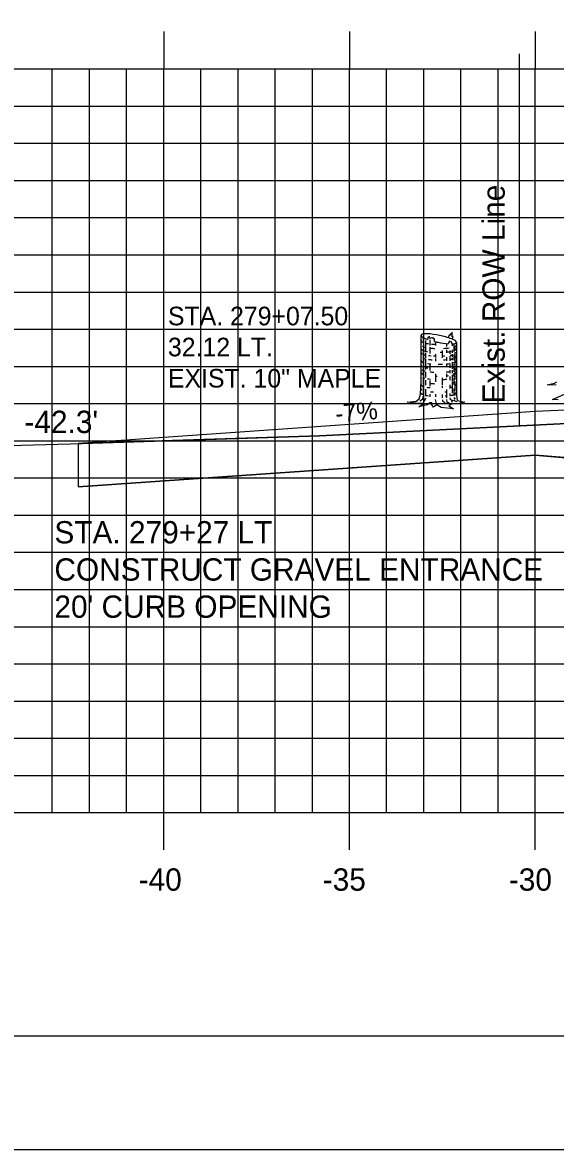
# Model space of a CAD drawing. Extents: x 854899 to 855069, y 366268 to 366378.
# Drawn here: x 854937.97 to 854952.32, y 366268.18 to 366298.48 of the extents above; entities that cross this region are included whole.
import ezdxf

# ---------------------------------------------------------------- set-up
doc = ezdxf.new("R2010")
doc.units = 0
for name, color, linetype in [('ANNOTATION', 7, 'Continuous'), ('BORDER', 7, 'Continuous'), ('D_Roadway_Drive_Gravel_LT', 7, 'Continuous'), ('D_Roadway_Drive_Gravel_RT', 7, 'Continuous'), ('D_Roadway_Drive_SubGrade', 7, 'Continuous'), ('D_Text_Monospaced', 7, 'Continuous'), ('D_Text_Standard', 7, 'Continuous'), ('E_ROW_Line', 7, 'Continuous'), ('H_V ANNOTATION', 7, 'Continuous'), ('JUNK COM EXC', 7, 'Continuous'), ('MAJOR', 7, 'Continuous'), ('MINOR', 7, 'Continuous'), ('PLOT BOUNDARY', 7, 'Continuous'), ('S_Roadway_Centerline', 7, 'Continuous'), ('S_Trees_Decid_NonPay', 7, 'Continuous'), ('S_Trees_Decid_Pay', 7, 'Continuous')]:
    doc.layers.add(name, color=color, linetype=linetype)

msp = doc.modelspace()

# ---------------------------------------------------------------- linework, layer by layer
at = {"layer": 'BORDER'}
msp.add_line((854906.774, 366271.236), (855066.774, 366271.236), dxfattribs=at)
at = {"layer": 'D_Roadway_Drive_Gravel_RT'}
for p, q in [((854957.774, 366288.264), (854951.774, 366288.024)), ((854951.774, 366288.024), (854939.471, 366287.163)), ((854951.774, 366286.853), (854939.471, 366285.996))]:
    msp.add_line(p, q, dxfattribs=at)
at = {"layer": 'D_Roadway_Drive_SubGrade'}
for p, q in [((854939.471, 366287.163), (854939.471, 366285.996)), ((854961.774, 366285.991), (854951.774, 366286.853))]:
    msp.add_line(p, q, dxfattribs=at)
at = {"layer": 'E_ROW_Line'}
msp.add_line((854951.351, 366287.638), (854951.351, 366297.638), dxfattribs=at)
at = {"layer": 'JUNK COM EXC'}
msp.add_lwpolyline([(854961.774, 366285.991), (854961.774, 366288.084), (854961.286, 366288.106), (854961.059, 366288.051), (854957.486, 366287.942), (854945.963, 366287.37), (854939.471, 366287.163), (854939.471, 366285.996), (854951.774, 366286.853)], close=True, dxfattribs=at)
at = {"layer": 'MAJOR'}
for p, q in [((854941.774, 366298.238), (854941.774, 366297.236)), ((854946.774, 366298.238), (854946.774, 366297.236)), ((854951.774, 366298.238), (854951.774, 366297.236)), ((854911.774, 366297.236), (855051.774, 366297.236)), ((854911.774, 366297.236), (855051.774, 366297.236)), ((854941.774, 366277.236), (854941.774, 366297.236)), ((854946.774, 366277.236), (854946.774, 366297.236)), ((854951.774, 366277.236), (854951.774, 366297.236)), ((854911.774, 366292.236), (855051.774, 366292.236)), ((854911.774, 366287.236), (855051.774, 366287.236)), ((854911.774, 366282.236), (855051.774, 366282.236)), ((854911.774, 366277.236), (855051.774, 366277.236)), ((854911.774, 366277.236), (855051.774, 366277.236)), ((854941.774, 366276.234), (854941.774, 366277.236)), ((854946.774, 366276.234), (854946.774, 366277.236)), ((854951.774, 366276.234), (854951.774, 366277.236))]:
    msp.add_line(p, q, dxfattribs=at)
at = {"layer": 'MINOR'}
for p, q in [((854938.774, 366277.236), (854938.774, 366297.236)), ((854939.774, 366277.236), (854939.774, 366297.236)), ((854940.774, 366277.236), (854940.774, 366297.236)), ((854942.774, 366277.236), (854942.774, 366297.236)), ((854943.774, 366277.236), (854943.774, 366297.236)), ((854944.774, 366277.236), (854944.774, 366297.236)), ((854945.774, 366277.236), (854945.774, 366297.236)), ((854947.774, 366277.236), (854947.774, 366297.236)), ((854948.774, 366277.236), (854948.774, 366297.236)), ((854949.774, 366277.236), (854949.774, 366297.236)), ((854950.774, 366277.236), (854950.774, 366297.236)), ((854911.774, 366296.236), (855051.774, 366296.236)), ((854911.774, 366295.236), (855051.774, 366295.236)), ((854911.774, 366294.236), (855051.774, 366294.236)), ((854911.774, 366293.236), (855051.774, 366293.236)), ((854911.774, 366291.236), (855051.774, 366291.236)), ((854911.774, 366290.236), (855051.774, 366290.236)), ((854911.774, 366289.236), (855051.774, 366289.236)), ((854911.774, 366288.236), (855051.774, 366288.236)), ((854911.774, 366286.236), (855051.774, 366286.236)), ((854911.774, 366285.236), (855051.774, 366285.236)), ((854911.774, 366284.236), (855051.774, 366284.236)), ((854911.774, 366283.236), (855051.774, 366283.236)), ((854911.774, 366281.236), (855051.774, 366281.236)), ((854911.774, 366280.236), (855051.774, 366280.236)), ((854911.774, 366279.236), (855051.774, 366279.236)), ((854911.774, 366278.236), (855051.774, 366278.236))]:
    msp.add_line(p, q, dxfattribs=at)
at = {"layer": 'PLOT BOUNDARY'}
msp.add_lwpolyline([(854898.681, 366268.177), (855068.681, 366268.177), (855068.681, 366378.177), (854898.681, 366378.177)], close=True, dxfattribs=at)
at = {"layer": 'S_Roadway_Centerline'}
msp.add_lwpolyline([(854920.631, 366286.642), (854924.888, 366286.755), (854939.58, 366287.166), (854945.963, 366287.37), (854957.486, 366287.942), (854961.059, 366288.051), (854961.286, 366288.106), (854963.414, 366288.013), (854965.316, 366287.948), (854966.506, 366288), (854971.338, 366288.32), (854977.246, 366288.416), (854982.457, 366288.64), (854989.068, 366288.497), (854993.573, 366288.403), (854996.105, 366288.282), (854996.433, 366288.257), (854999.77, 366288.409), (854999.893, 366288.419), (855006.72, 366288.819), (855009.438, 366288.75)], dxfattribs=at)
at = {"layer": 'S_Trees_Decid_NonPay'}
for p, q in [((854948.753, 366290.016), (854948.753, 366289.922)), ((854948.753, 366289.695), (854948.753, 366289.613)), ((854948.821, 366289.929), (854948.821, 366289.629)), ((854948.94, 366289.947), (854948.94, 366289.798)), ((854948.94, 366289.75), (854948.94, 366289.582)), ((854949.087, 366289.901), (854949.087, 366289.794)), ((854949.267, 366289.664), (854949.267, 366289.464)), ((854949.384, 366289.848), (854949.384, 366289.769)), ((854949.384, 366289.683), (854949.384, 366289.598)), ((854949.471, 366289.664), (854949.471, 366289.578)), ((854949.541, 366289.838), (854949.541, 366289.786)), ((854949.541, 366289.683), (854949.541, 366289.6)), ((854949.584, 366289.843), (854949.584, 366289.625)), ((854949.611, 366289.773), (854949.611, 366289.691)), ((854948.753, 366289.543), (854948.753, 366289.292)), ((854948.821, 366289.6), (854948.821, 366289.469)), ((854948.821, 366289.435), (854948.821, 366289.154)), ((854949.087, 366289.565), (854949.087, 366289.479)), ((854949.087, 366289.444), (854949.087, 366289.374)), ((854949.384, 366289.487), (854949.384, 366289.386)), ((854949.471, 366289.508), (854949.471, 366289.386)), ((854949.541, 366289.565), (854949.541, 366289.491)), ((854949.541, 366289.464), (854949.541, 366289.405)), ((854949.541, 366289.351), (854949.541, 366289.17)), ((854949.584, 366289.556), (854949.584, 366289.405)), ((854949.611, 366289.621), (854949.611, 366289.491)), ((854949.611, 366289.469), (854949.611, 366289.287)), ((854948.753, 366289.209), (854948.753, 366288.979)), ((854948.821, 366289.084), (854948.821, 366288.939)), ((854948.94, 366289.275), (854948.94, 366289.127)), ((854949.384, 366289.301), (854949.384, 366289.225)), ((854949.471, 366289.311), (854949.471, 366289.197)), ((854949.471, 366289.135), (854949.471, 366289.053)), ((854949.541, 366289.139), (854949.541, 366289.057)), ((854949.584, 366289.3), (854949.584, 366289.221)), ((854949.584, 366289.195), (854949.584, 366289.088)), ((854949.584, 366289.053), (854949.584, 366288.952)), ((854949.611, 366289.24), (854949.611, 366288.993)), ((854948.753, 366288.908), (854948.753, 366288.748)), ((854948.821, 366288.869), (854948.821, 366288.727)), ((854948.94, 366288.857), (854948.94, 366288.704)), ((854949.087, 366289.04), (854949.087, 366288.818)), ((854949.267, 366288.927), (854949.267, 366288.74)), ((854949.384, 366289.04), (854949.384, 366288.943)), ((854949.471, 366288.966), (854949.471, 366288.869)), ((854949.471, 366288.74), (854949.471, 366288.641)), ((854949.541, 366289.003), (854949.541, 366288.832)), ((854949.541, 366288.799), (854949.541, 366288.519)), ((854949.584, 366288.926), (854949.584, 366288.744)), ((854949.611, 366288.974), (854949.611, 366288.88)), ((854949.613, 366288.826), (854949.612, 366288.567)), ((854948.753, 366288.731), (854948.753, 366288.626)), ((854948.753, 366288.59), (854948.753, 366288.466)), ((854948.821, 366288.626), (854948.821, 366288.445)), ((854948.94, 366288.492), (854948.94, 366288.414)), ((854949.087, 366288.485), (854949.087, 366288.418)), ((854949.267, 366288.709), (854949.267, 366288.656)), ((854949.267, 366288.48), (854949.267, 366288.389)), ((854949.384, 366288.618), (854949.384, 366288.394)), ((854949.471, 366288.511), (854949.471, 366288.453)), ((854949.541, 366288.467), (854949.541, 366288.441)), ((854949.584, 366288.641), (854949.584, 366288.449)), ((854949.611, 366288.528), (854949.611, 366288.454)), ((854948.82, 366288.385), (854948.779, 366288.289)), ((854949.127, 366288.198), (854949.092, 366288.344)), ((854949.582, 366288.402), (854949.617, 366288.351)), ((854949.664, 366288.28), (854949.597, 366288.311))]:
    msp.add_line(p, q, dxfattribs=at)
for points in [[(854949.652, 366289.88), (854949.652, 366288.468), (854949.675, 366288.32), (854949.878, 366288.277), (854949.738, 366288.241), (854949.52, 366288.223), (854949.45, 366288.179), (854949.572, 366288.091), (854949.24, 366288.134), (854949.127, 366288.198), (854949.034, 366288.138), (854948.978, 366288.217), (854948.987, 366288.254), (854948.925, 366288.256), (854948.873, 366288.198), (854948.641, 366288.147), (854948.768, 366288.235), (854948.637, 366288.237), (854948.328, 366288.275), (854948.567, 366288.305), (854948.645, 366288.363), (854948.684, 366288.485), (854948.701, 366288.838), (854948.701, 366290.072)], [(854949.065, 366289.906), (854949.057, 366289.973), (854949.032, 366289.977), (854949.024, 366290.012), (854948.993, 366289.998), (854948.978, 366290.012), (854948.954, 366289.989), (854948.931, 366289.998), (854948.919, 366290.047), (854948.911, 366290.004), (854948.88, 366290.012), (854948.877, 366289.961)], [(854949.557, 366289.961), (854949.553, 366290.055), (854949.539, 366290.029), (854949.539, 366290.15), (854949.518, 366290.086), (854949.503, 366290.119), (854949.487, 366290.063), (854949.471, 366290.08), (854949.452, 366290.072), (854949.433, 366290.005)], [(854949.535, 366289.837), (854949.518, 366289.899), (854949.496, 366289.887), (854949.465, 366289.922), (854949.431, 366289.843)], [(854948.75, 366288.423), (854948.742, 366288.346), (854948.663, 366288.297)], [(854949.275, 366288.34), (854949.275, 366288.303), (854949.326, 366288.273), (854949.343, 366288.223)], [(854949.387, 366288.346), (854949.392, 366288.277), (854949.456, 366288.264)], [(854949.534, 366288.311), (854949.491, 366288.346), (854949.483, 366288.394)], [(854949.613, 366288.328), (854949.534, 366288.311), (854949.518, 366288.268)]]:
    msp.add_lwpolyline(points, dxfattribs=at)
for centre, radius, start, end in [((854948.719, 366290.072), 0.0179, 168.1723, 184.2278), ((854948.725, 366290.072), 0.0237, 184.2278, 198.1723), ((854948.719, 366290.072), 0.0179, 152.1168, 168.1723), ((854948.734, 366290.075), 0.0336, 198.1723, 216.9486), ((854948.724, 366290.069), 0.0237, 138.1723, 152.1168), ((854948.732, 366290.063), 0.0336, 119.396, 138.1723), ((854948.782, 366290.111), 0.0935, 216.9486, 228.1723), ((854948.761, 366290.01), 0.0935, 108.1723, 119.396), ((854948.934, 366290.282), 0.322, 228.1723, 250.2902), ((854948.832, 366289.793), 0.322, 86.0543, 108.1723), ((854949.671, 366292.339), 2.507, 250.2902, 251.5281), ((854948.682, 366287.614), 2.507, 78.1723, 86.0543), ((854948.682, 366287.614), 2.507, 70.2902, 78.1723), ((854949.419, 366289.671), 0.322, 48.1723, 70.2902), ((854948.719, 366289.924), 0.0191, 163.9485, 180), ((854948.719, 366289.924), 0.0191, 180, 196.0515), ((854948.719, 366289.71), 0.0191, 163.9485, 180), ((854948.719, 366289.71), 0.0191, 180, 196.0515), ((854948.725, 366289.926), 0.0252, 196.0515, 210), ((854948.725, 366289.712), 0.0252, 196.0515, 210), ((854948.734, 366289.931), 0.0356, 210, 228.7494), ((854948.734, 366289.717), 0.0356, 210, 228.7494), ((854948.776, 366289.979), 0.0984, 228.7494, 240), ((854948.776, 366289.764), 0.0984, 228.7494, 240), ((854948.89, 366290.176), 0.326, 240, 248.3243), ((854948.89, 366289.962), 0.326, 240, 243.5719), ((854948.89, 366290.063), 0.326, 240.9099, 257.8036), ((854948.89, 366289.962), 0.326, 250.4167, 261.8968), ((854948.89, 366290.176), 0.326, 257.8036, 261.8968), ((854949.176, 366292.186), 2.356, 261.8968, 263.2799), ((854949.176, 366292.073), 2.356, 264.242, 267.3673), ((854949.176, 366292.186), 2.356, 265.24, 267.8386), ((854949.671, 366292.339), 2.507, 255.9987, 258.1723), ((854949.671, 366292.339), 2.507, 258.1723, 264.5013), ((854949.176, 366292.073), 2.356, 273.1481, 276.7734), ((854949.521, 366290.159), 0.322, 272.4479, 288.1723), ((854949.462, 366290.063), 0.326, 291.9506, 300), ((854949.462, 366289.962), 0.326, 291.9506, 300), ((854949.592, 366289.942), 0.0935, 288.1723, 299.396), ((854949.576, 366289.865), 0.0984, 300, 311.2506), ((854949.576, 366289.764), 0.0984, 300, 311.2506), ((854949.571, 366289.841), 0.0935, 36.9486, 48.1723), ((854949.622, 366289.89), 0.0336, 299.396, 318.1723), ((854949.617, 366289.818), 0.0356, 311.2506, 330), ((854949.617, 366289.717), 0.0356, 311.2506, 330), ((854949.619, 366289.877), 0.0336, 18.1723, 36.9486), ((854949.629, 366289.883), 0.0237, 318.1723, 332.1168), ((854949.626, 366289.813), 0.0252, 330, 343.9485), ((854949.626, 366289.712), 0.0252, 330, 343.9485), ((854949.634, 366289.88), 0.0179, 332.1168, 348.1723), ((854949.628, 366289.88), 0.0237, 4.2278, 18.1723), ((854949.632, 366289.811), 0.0191, 360, 6.1128), ((854949.632, 366289.811), 0.0191, 343.9485, 360), ((854949.632, 366289.71), 0.0191, 360, 6.1128), ((854949.632, 366289.71), 0.0191, 343.9485, 360), ((854949.634, 366289.88), 0.0179, 348.1723, 4.2278), ((854948.719, 366289.607), 0.0191, 163.9485, 180), ((854948.719, 366289.607), 0.0191, 180, 196.0515), ((854948.719, 366289.387), 0.0191, 163.9485, 180), ((854948.719, 366289.387), 0.0191, 180, 196.0515), ((854948.725, 366289.609), 0.0252, 196.0515, 210), ((854948.725, 366289.389), 0.0252, 196.0515, 210), ((854948.734, 366289.614), 0.0356, 210, 228.7494), ((854948.734, 366289.394), 0.0356, 210, 228.7494), ((854948.776, 366289.662), 0.0984, 228.7494, 240), ((854948.776, 366289.441), 0.0984, 228.7494, 240), ((854948.89, 366289.859), 0.326, 240, 243.243), ((854948.89, 366289.639), 0.326, 240, 245.1545), ((854948.89, 366289.754), 0.326, 245.1545, 257.8036), ((854948.89, 366289.859), 0.326, 251.6831, 257.8036), ((854949.176, 366291.972), 2.356, 261.8968, 262.5519), ((854949.176, 366291.764), 2.356, 263.2682, 265.6362), ((854949.176, 366291.869), 2.356, 263.3413, 264.9946), ((854949.176, 366291.869), 2.356, 266.5036, 267.8386), ((854949.176, 366291.972), 2.356, 270.8119, 272.1981), ((854949.176, 366291.869), 2.356, 272.1981, 273.9741), ((854949.176, 366291.764), 2.356, 273.0067, 275.0647), ((854949.176, 366291.972), 2.356, 275.0647, 278.1032), ((854949.176, 366291.764), 2.356, 277.1868, 278.1032), ((854949.176, 366291.869), 2.356, 277.3838, 278.1032), ((854949.462, 366289.962), 0.326, 278.1032, 279.0854), ((854949.462, 366289.859), 0.326, 278.1032, 284.0382), ((854949.462, 366289.754), 0.326, 278.1032, 284.0382), ((854949.462, 366289.639), 0.326, 284.0382, 300), ((854949.462, 366289.754), 0.326, 291.9506, 300), ((854949.576, 366289.557), 0.0984, 300, 311.2506), ((854949.576, 366289.441), 0.0984, 300, 311.2506), ((854949.617, 366289.509), 0.0356, 311.2506, 330), ((854949.617, 366289.394), 0.0356, 311.2506, 330), ((854949.626, 366289.504), 0.0252, 330, 343.9485), ((854949.626, 366289.389), 0.0252, 330, 343.9485), ((854949.632, 366289.607), 0.0191, 360, 6.1128), ((854949.632, 366289.607), 0.0191, 343.9485, 360), ((854949.632, 366289.502), 0.0191, 360, 6.1128), ((854949.632, 366289.502), 0.0191, 343.9485, 360), ((854949.632, 366289.387), 0.0191, 360, 6.1128), ((854949.632, 366289.387), 0.0191, 343.9485, 360), ((854948.717, 366289.173), 0.0191, 163.9485, 180), ((854948.719, 366289.068), 0.0191, 163.9485, 180), ((854948.719, 366289.068), 0.0191, 180, 196.0515), ((854948.72, 366289.273), 0.0191, 163.9485, 180), ((854948.72, 366289.273), 0.0191, 180, 196.0515), ((854948.725, 366289.07), 0.0252, 196.0515, 210), ((854948.726, 366289.275), 0.0252, 196.0515, 210), ((854948.735, 366289.28), 0.0356, 210, 228.7494), ((854948.734, 366289.075), 0.0356, 210, 228.7494), ((854948.776, 366289.122), 0.0984, 228.7494, 240), ((854948.777, 366289.327), 0.0984, 228.7494, 240), ((854948.887, 366289.424), 0.326, 240, 256.9079), ((854948.89, 366289.524), 0.326, 240, 247.8656), ((854948.89, 366289.524), 0.326, 257.6699, 261.8968), ((854949.177, 366291.534), 2.356, 261.8968, 262.8615), ((854949.176, 366291.649), 2.356, 262.6588, 264.7911), ((854949.173, 366291.434), 2.356, 264.3443, 266.8529), ((854949.176, 366291.649), 2.356, 269.5578, 270), ((854949.176, 366291.649), 2.356, 270, 272.414), ((854949.173, 366291.434), 2.356, 274.9734, 277.2455), ((854949.176, 366291.649), 2.356, 275.0647, 277.1868), ((854949.463, 366289.524), 0.326, 283.9036, 291.8098), ((854949.46, 366289.424), 0.326, 292.4049, 300), ((854949.463, 366289.524), 0.326, 297.0058, 300), ((854949.573, 366289.227), 0.0984, 300, 311.2506), ((854949.576, 366289.122), 0.0984, 300, 311.2506), ((854949.577, 366289.327), 0.0984, 300, 311.2506), ((854949.615, 366289.18), 0.0356, 311.2506, 330), ((854949.617, 366289.075), 0.0356, 311.2506, 330), ((854949.618, 366289.28), 0.0356, 311.2506, 330), ((854949.624, 366289.174), 0.0252, 330, 343.9485), ((854949.63, 366289.173), 0.0191, 343.9485, 360), ((854949.626, 366289.07), 0.0252, 330, 343.9485), ((854949.627, 366289.275), 0.0252, 330, 343.9485), ((854949.63, 366289.173), 0.0191, 0, 6.1128), ((854949.633, 366289.273), 0.0191, 343.9485, 360), ((854949.632, 366289.068), 0.0191, 360, 6.1128), ((854949.632, 366289.068), 0.0191, 343.9485, 360), ((854949.633, 366289.273), 0.0191, 0, 6.1128), ((854948.715, 366288.749), 0.0191, 163.9485, 180), ((854948.715, 366288.749), 0.0191, 180, 196.0515), ((854948.721, 366288.751), 0.0252, 196.0515, 210), ((854948.73, 366288.756), 0.0356, 210, 228.7494), ((854948.89, 366289.319), 0.326, 240, 245.1545), ((854948.89, 366289.229), 0.326, 241.939, 253.9183), ((854949.176, 366291.239), 2.356, 262.5843, 264.4865), ((854949.176, 366291.125), 2.356, 264.242, 267.469), ((854949.176, 366291.329), 2.356, 267.8386, 269.0054), ((854949.176, 366291.239), 2.356, 272.1981, 275.2726), ((854949.176, 366291.329), 2.356, 275.0647, 276.428), ((854949.462, 366289.319), 0.326, 284.0382, 291.9506), ((854949.462, 366289.115), 0.326, 284.0382, 291.9506), ((854949.462, 366289.319), 0.326, 297.1525, 300), ((854949.613, 366288.756), 0.0356, 311.2506, 330), ((854949.622, 366288.751), 0.0252, 330, 343.9485), ((854949.628, 366288.749), 0.0191, 343.9485, 360), ((854949.628, 366288.749), 0.0191, 360, 6.1128), ((854949.632, 366288.977), 0.0191, 360, 6.1128), ((854948.705, 366288.528), 0.0191, 163.9485, 180), ((854948.705, 366288.528), 0.0191, 180, 196.0515), ((854948.711, 366288.53), 0.0252, 196.0515, 210), ((854948.72, 366288.535), 0.0356, 210, 228.7494), ((854948.711, 366288.638), 0.0191, 163.9485, 180), ((854948.711, 366288.638), 0.0191, 180, 196.0515), ((854948.716, 366288.64), 0.0252, 196.0515, 210), ((854948.725, 366288.645), 0.0356, 210, 228.7494), ((854948.761, 366288.582), 0.0984, 228.7494, 240), ((854948.767, 366288.692), 0.0984, 228.7494, 240), ((854948.772, 366288.803), 0.0984, 228.7494, 240), ((854948.875, 366288.779), 0.326, 240, 247.9161), ((854948.881, 366288.89), 0.326, 240, 241.9097), ((854948.886, 366289), 0.326, 240, 245.9375), ((854948.875, 366288.779), 0.326, 260.3834, 261.8968), ((854949.161, 366290.789), 2.356, 261.8968, 263.5333), ((854949.172, 366291.01), 2.356, 262.2226, 264.4852), ((854949.167, 366290.9), 2.356, 264.9089, 266.8158), ((854949.167, 366290.9), 2.356, 274.1864, 275.2829), ((854949.161, 366290.789), 2.356, 274.5551, 275.4167), ((854949.172, 366291.01), 2.356, 277.2863, 278.1032), ((854949.161, 366290.789), 2.356, 277.5403, 278.1032), ((854949.448, 366288.779), 0.326, 278.1032, 294.7094), ((854949.458, 366289), 0.326, 278.1032, 284.7741), ((854949.453, 366288.89), 0.326, 293.6544, 300), ((854949.561, 366288.582), 0.0984, 300, 311.2506), ((854949.572, 366288.803), 0.0984, 300, 311.2506), ((854949.603, 366288.535), 0.0356, 311.2506, 330), ((854949.612, 366288.53), 0.0252, 330, 343.9485), ((854949.618, 366288.528), 0.0191, 343.9485, 360), ((854949.618, 366288.528), 0.0191, 0, 6.1128)]:
    msp.add_arc(centre, radius, start, end, dxfattribs=at)
at = {"layer": 'S_Trees_Decid_Pay'}
for points in [[(854952.338, 366288.732), (854952.097, 366288.744), (854952.295, 366288.781), (854952.357, 366288.818)], [(854952.393, 366288.334), (854952.239, 366288.347), (854952.581, 366288.497)]]:
    msp.add_lwpolyline(points, dxfattribs=at)

# ---------------------------------------------------------------- texts
at = {"layer": 'ANNOTATION'}
for s, p in [('STA. 279+27 LT', (854938.833, 366284.475)), ('CONSTRUCT GRAVEL ENTRANCE', (854938.833, 366283.475)), ("20' CURB OPENING", (854938.833, 366282.475))]:
    msp.add_text(s, height=0.6, dxfattribs=at).set_placement(p)
at = {"layer": 'D_Roadway_Drive_Gravel_LT'}
msp.add_text('-7%', height=0.48, rotation=5.1428, dxfattribs=at).set_placement((854946.413, 366287.72))
at = {"layer": 'D_Text_Monospaced'}
for s, height, p in [('STA. 279+07.50', 0.49998, (854941.888, 366290.341)), ('32.12 LT.', 0.5, (854941.888, 366289.507)), ('EXIST. 10" MAPLE', 0.49998, (854941.888, 366288.667))]:
    msp.add_text(s, height=height, dxfattribs=at).set_placement(p)
at = {"layer": 'D_Text_Standard'}
msp.add_text("-42.3'", height=0.6, dxfattribs=at).set_placement((854938.027, 366287.445))
at = {"layer": 'E_ROW_Line'}
msp.add_text('Exist. ROW Line', height=0.6, rotation=90, dxfattribs=at).set_placement((854950.951, 366288.238))
at = {"layer": 'H_V ANNOTATION'}
for s, p in [('-40', (854941.1, 366275.136)), ('-35', (854946.054, 366275.136)), ('-30', (854951.062, 366275.136))]:
    msp.add_text(s, height=0.6, dxfattribs=at).set_placement(p)

doc.saveas('drawing.dxf')
